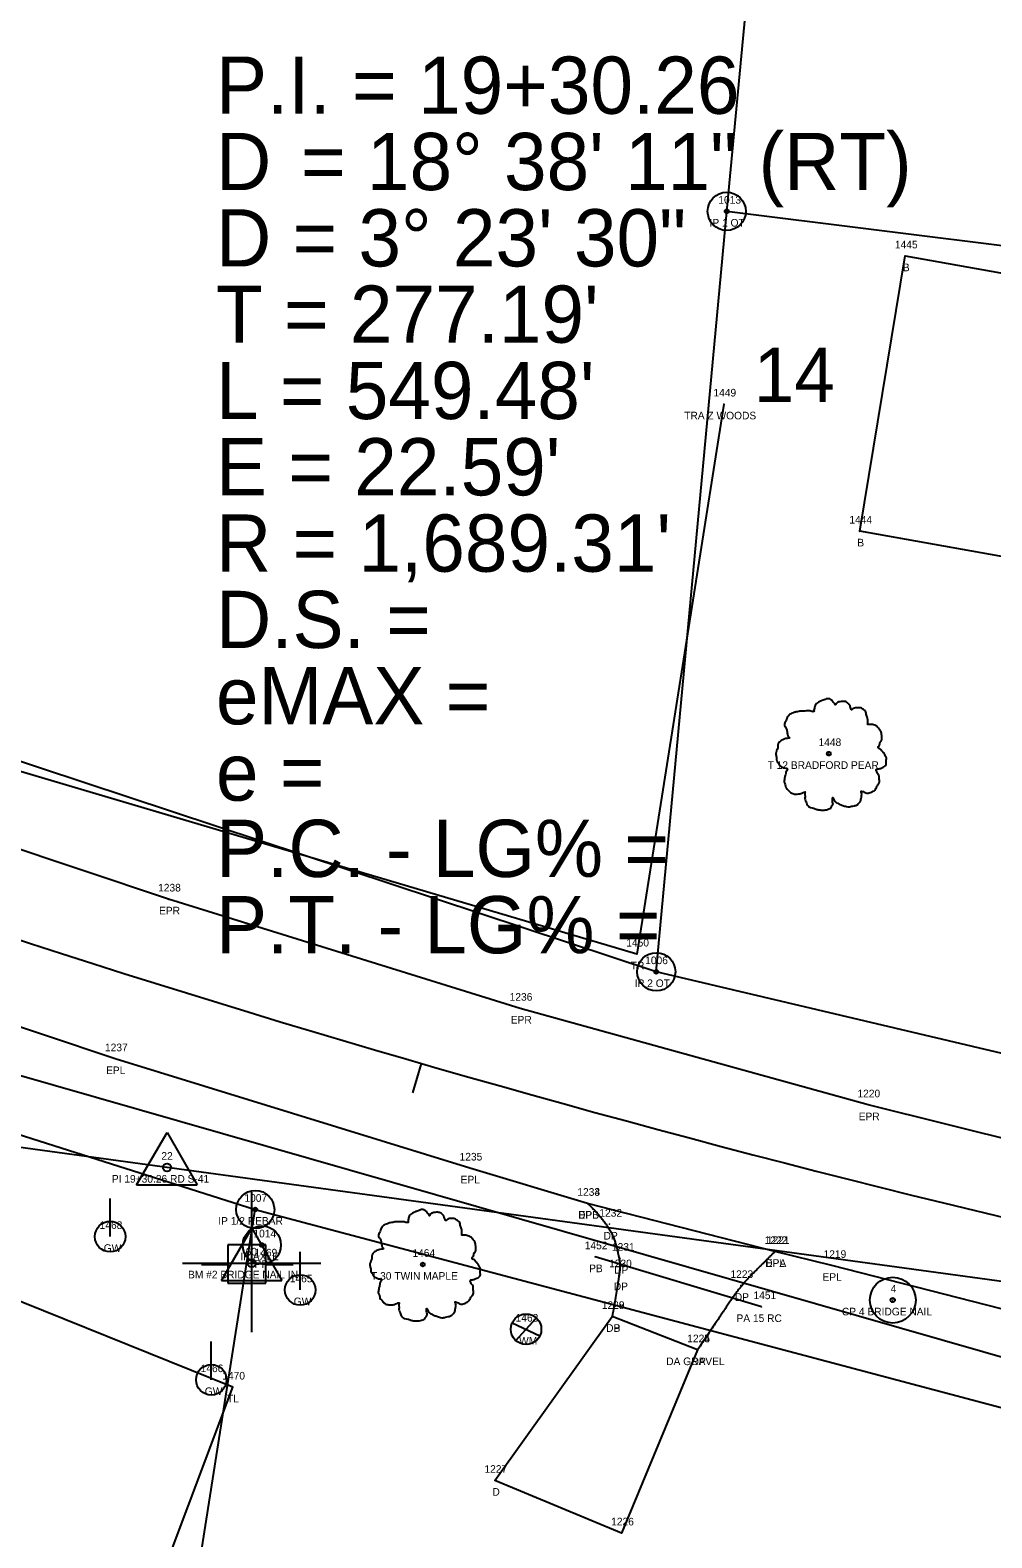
# Model space of a CAD drawing. Extents: x 1812113 to 1819860, y 1177395 to 1181185.
# Drawn here: x 1813245.7 to 1813371.7, y 1178760.4 to 1178958 of the extents above; entities that cross this region are included whole.
import ezdxf

# ---------------------------------------------------------------- set-up
doc = ezdxf.new("R2010")
doc.units = 0
for name, color, linetype in [('RD_EX_Bldg', 7, 'Continuous'), ('RD_EX_Bldg_txCode', 7, 'Continuous'), ('RD_EX_DR_Pipe', 7, 'Continuous'), ('RD_EX_DR_Pipe_txCode', 7, 'Continuous'), ('RD_EX_Driveway', 7, 'Continuous'), ('RD_EX_Driveway_txCode', 7, 'Continuous'), ('RD_EX_DV_Prop', 7, 'Continuous'), ('RD_EX_DV_Prop_txCode', 7, 'Continuous'), ('RD_EX_DV_PropPin', 7, 'Continuous'), ('RD_EX_DV_TX_Prop', 7, 'Continuous'), ('RD_EX_Road', 7, 'Continuous'), ('RD_EX_Road_txCode', 7, 'Continuous'), ('RD_EX_UT', 7, 'Continuous'), ('RD_EX_UT_txCode', 7, 'Continuous'), ('RD_EX_VEG', 7, 'Continuous'), ('RD_EX_VEG_txCode', 7, 'Continuous'), ('RD_HC_CL', 7, 'Continuous'), ('RD_HC_Data', 7, 'Continuous'), ('RD_HC_Data_Tic', 7, 'Continuous'), ('RD_HC_TX_StaOther', 7, 'Continuous'), ('RD_HC_txCode', 7, 'Continuous'), ('RD_PD_PatLn1', 7, 'Continuous'), ('RD_SMD_Locator', 7, 'Continuous')]:
    doc.layers.add(name, color=color, linetype=linetype)

msp = doc.modelspace()

# ---------------------------------------------------------------- linework, layer by layer
at = {"layer": 'RD_EX_Bldg'}
msp.add_lwpolyline([(1813386.16, 1178886.63), (1813354.34, 1178892.31), (1813360.31, 1178928.37), (1813392.12, 1178922.69), (1813386.16, 1178886.63)], dxfattribs=at)
at = {"layer": 'RD_EX_DR_Pipe'}
msp.add_line((1813341.49, 1178790.69), (1813319.67, 1178797.22), dxfattribs=at)
at = {"layer": 'RD_EX_Driveway'}
msp.add_line((1813333.1, 1178785.04), (1813321.9, 1178789.4), dxfattribs=at)
msp.add_lwpolyline([(1813333.1, 1178785.04), (1813323.15, 1178761.04), (1813306.52, 1178767.93), (1813321.9, 1178789.4)], dxfattribs=at)
for points in [[(1813318.7, 1178804.23), (1813321.57, 1178801.49), (1813322.95, 1178797.03), (1813322.9, 1178794.86), (1813321.9, 1178789.4)], [(1813343.23, 1178797.92), (1813341, 1178795.69), (1813338.76, 1178793.46), (1813335.93, 1178789.25), (1813333.1, 1178785.04)]]:
    msp.add_open_spline(points, degree=2, dxfattribs=at)
at = {"layer": 'RD_EX_DV_Prop'}
for p, q in [((1813336.92, 1178934.22), (1813350.46, 1179077.16)), ((1813327.69, 1178834.58), (1813336.92, 1178934.22)), ((1813428.23, 1178922.79), (1813336.92, 1178934.22)), ((1813327.69, 1178834.58), (1813191.92, 1178879.48)), ((1813136.34, 1178847.55), (1813275.15, 1178803.43)), ((1813400.47, 1178817.38), (1813327.69, 1178834.58)), ((1813247.98, 1178630.56), (1813275.15, 1178803.43)), ((1813275.15, 1178803.43), (1813409.98, 1178767.65))]:
    msp.add_line(p, q, dxfattribs=at)
at = {"layer": 'RD_EX_DV_PropPin'}
for centre, radius in [((1813336.92, 1178934.22), 2.5), ((1813336.92, 1178934.22), 0.25), ((1813327.69, 1178834.58), 2.5), ((1813327.69, 1178834.58), 0.25), ((1813275.15, 1178803.43), 2.5), ((1813275.15, 1178803.43), 0.25), ((1813276.02, 1178798.78), 2.5), ((1813276.02, 1178798.78), 0.25)]:
    msp.add_circle(centre, radius, dxfattribs=at)
at = {"layer": 'RD_EX_Road'}
for p, q in [((1813263.76, 1178844.1), (1813216.84, 1178859.81)), ((1813309.85, 1178829.79), (1813263.76, 1178844.1)), ((1813355.44, 1178817.13), (1813309.85, 1178829.79)), ((1813398.64, 1178806.42), (1813355.44, 1178817.13))]:
    msp.add_line(p, q, dxfattribs=at)
msp.add_lwpolyline([(1813732.94, 1178707.95), (1813689.88, 1178731.75), (1813641.71, 1178744.36), (1813593.37, 1178752.09), (1813544.49, 1178758.77), (1813495.45, 1178766.29), (1813446.8, 1178774.66), (1813426.54, 1178777.95), (1813403.21, 1178782.55), (1813398.65, 1178783.84), (1813350.68, 1178796.09), (1813343.23, 1178797.92), (1813318.7, 1178804.23), (1813303.26, 1178808.85), (1813256.8, 1178823.17), (1813209.81, 1178838.91), (1813163.27, 1178855.57)], dxfattribs=at)
at = {"layer": 'RD_EX_UT'}
for p, q in [((1813256.13, 1178799.88), (1813256.13, 1178804.88)), ((1813276.55, 1178798.79), (1813271.55, 1178798.79)), ((1813271.55, 1178798.79), (1813271.55, 1178793.79)), ((1813276.55, 1178793.79), (1813276.55, 1178798.79)), ((1813281.04, 1178792.89), (1813281.04, 1178797.89)), ((1813268.12, 1178796.23), (1813271.59, 1178796.23)), ((1813276.48, 1178796.23), (1813280.12, 1178796.23)), ((1813271.55, 1178793.79), (1813276.55, 1178793.79)), ((1813309.28, 1178786.28), (1813311.94, 1178789.18)), ((1813308.79, 1178788.58), (1813312.43, 1178786.87)), ((1813269.39, 1178781.12), (1813269.39, 1178786.12))]:
    msp.add_line(p, q, dxfattribs=at)
msp.add_lwpolyline([(1812996.89, 1178919.95), (1813204.49, 1178832.44), (1813481.3, 1178753.03), (1813490.2, 1178706.76)], dxfattribs=at)
for centre in [(1813256.13, 1178799.88), (1813281.04, 1178792.89), (1813310.63, 1178787.74), (1813269.39, 1178781.12)]:
    msp.add_circle(centre, 2, dxfattribs=at)
at = {"layer": 'RD_EX_VEG'}
for points in [[(1813336.53, 1178908.96), (1813325.15, 1178836.89), (1813188.47, 1178877.39), (1813208.68, 1178923.85)], [(1813260.51, 1178748.95), (1813272.22, 1178780.15), (1813153.76, 1178827.9)]]:
    msp.add_lwpolyline(points, dxfattribs=at)
for centre, radius in [((1813350.3, 1178863.16), 0.25), ((1813350.28, 1178863.14), 0.0001), ((1813297.11, 1178796.23), 0.25), ((1813297.1, 1178796.21), 0.0001)]:
    msp.add_circle(centre, radius, dxfattribs=at)
for points in [[(1813350.43, 1178870.33), (1813350.13, 1178870.36), (1813349.8, 1178870.26), (1813349.55, 1178870.16), (1813349.33, 1178870.08), (1813349.1, 1178869.98), (1813348.8, 1178869.81), (1813348.58, 1178869.61), (1813348.45, 1178869.36), (1813348.4, 1178869.13), (1813348.35, 1178868.86), (1813348.35, 1178868.68), (1813348.23, 1178868.66), (1813348.08, 1178868.68), (1813347.83, 1178868.76), (1813347.58, 1178868.76), (1813347.33, 1178868.76), (1813346.98, 1178868.73), (1813346.63, 1178868.73), (1813346.35, 1178868.68), (1813346.03, 1178868.63), (1813345.65, 1178868.51), (1813345.3, 1178868.38), (1813345, 1178868.13), (1813344.75, 1178867.66), (1813344.63, 1178867.31), (1813344.48, 1178867.06), (1813344.63, 1178866.61), (1813344.8, 1178866.26), (1813344.83, 1178866.06), (1813344.9, 1178865.63), (1813345, 1178865.41), (1813345.13, 1178865.21), (1813345.05, 1178865.18), (1813344.68, 1178865.13), (1813344.38, 1178865.03), (1813343.95, 1178864.81), (1813343.73, 1178864.58), (1813343.63, 1178864.26), (1813343.61, 1178863.91), (1813343.51, 1178863.71), (1813343.43, 1178863.43), (1813343.41, 1178863.36), (1813343.36, 1178863.03), (1813343.46, 1178862.58), (1813343.48, 1178862.23), (1813343.61, 1178862.01), (1813343.75, 1178861.83), (1813343.93, 1178861.58), (1813344.33, 1178861.36), (1813344.65, 1178861.26), (1813344.85, 1178861.23), (1813344.68, 1178860.73), (1813344.63, 1178860.38), (1813344.5, 1178859.98), (1813344.5, 1178859.91), (1813344.45, 1178859.43), (1813344.6, 1178859.11), (1813344.68, 1178858.74), (1813344.85, 1178858.51), (1813345.13, 1178858.21), (1813345.45, 1178857.99), (1813345.95, 1178857.86), (1813346.35, 1178857.89), (1813346.93, 1178858.06), (1813347.18, 1178858.14), (1813347.15, 1178857.96), (1813347.18, 1178857.59), (1813347.18, 1178857.16), (1813347.33, 1178856.84), (1813347.43, 1178856.56), (1813347.58, 1178856.31), (1813347.9, 1178856.09), (1813348.3, 1178856.01), (1813348.73, 1178855.86), (1813349.18, 1178855.79), (1813349.68, 1178855.76), (1813350.28, 1178855.91), (1813350.55, 1178856.04), (1813350.65, 1178856.21), (1813350.85, 1178856.59), (1813350.8, 1178856.81), (1813350.83, 1178857.41), (1813350.93, 1178857.24), (1813351.1, 1178856.89), (1813351.6, 1178856.59), (1813352, 1178856.41), (1813352.48, 1178856.26), (1813352.78, 1178856.19), (1813353.25, 1178856.26), (1813353.63, 1178856.34), (1813354, 1178856.46), (1813354.3, 1178856.74), (1813354.48, 1178857.01), (1813354.53, 1178857.29), (1813354.6, 1178857.66), (1813354.65, 1178857.84)], [(1813354.65, 1178857.84), (1813354.58, 1178858.01), (1813354.53, 1178858.26), (1813354.6, 1178858.24), (1813354.78, 1178858.19), (1813355.05, 1178858.06), (1813355.27, 1178857.99), (1813355.6, 1178858.01), (1813355.87, 1178858.11), (1813356.32, 1178858.39), (1813356.6, 1178858.86), (1813356.87, 1178859.26), (1813356.95, 1178859.58), (1813356.9, 1178859.81), (1813356.87, 1178860.31), (1813356.67, 1178860.56), (1813356.62, 1178860.68), (1813356.52, 1178861.08), (1813356.6, 1178861.13), (1813356.87, 1178861.18), (1813357.25, 1178861.31), (1813357.52, 1178861.43), (1813357.75, 1178861.61), (1813357.82, 1178861.83), (1813357.8, 1178862.23), (1813357.85, 1178862.63), (1813357.77, 1178862.78), (1813357.67, 1178862.93), (1813357.6, 1178863.13), (1813357.45, 1178863.28), (1813357.35, 1178863.43), (1813357.25, 1178863.53), (1813357.12, 1178863.68), (1813356.95, 1178863.81), (1813356.8, 1178863.86), (1813356.75, 1178864.01), (1813356.9, 1178864.21), (1813356.95, 1178864.31), (1813356.97, 1178864.53), (1813357.2, 1178864.88), (1813357.25, 1178865.28), (1813357.2, 1178865.71), (1813357.15, 1178865.98), (1813357, 1178866.26), (1813356.8, 1178866.51), (1813356.67, 1178866.68), (1813356.5, 1178866.81), (1813356.17, 1178866.93), (1813355.92, 1178866.98), (1813355.57, 1178866.98), (1813355.37, 1178867.03), (1813355.4, 1178867.08), (1813355.4, 1178867.23), (1813355.4, 1178867.51), (1813355.32, 1178867.96), (1813355.17, 1178868.46), (1813355.17, 1178868.48), (1813355.07, 1178868.73), (1813354.85, 1178868.93), (1813354.68, 1178869.03), (1813354.48, 1178869.16), (1813354.23, 1178869.18), (1813353.93, 1178869.18), (1813353.65, 1178869.13), (1813353.45, 1178869.03), (1813353.28, 1178868.91), (1813353.2, 1178869.06), (1813353.1, 1178869.36), (1813353.05, 1178869.51), (1813352.9, 1178869.68), (1813352.68, 1178869.88), (1813352.23, 1178870.01), (1813351.6, 1178869.93), (1813351.3, 1178869.73), (1813351.15, 1178869.56), (1813351.1, 1178869.68), (1813350.9, 1178869.88), (1813350.8, 1178870.06), (1813350.63, 1178870.18), (1813350.48, 1178870.28), (1813350.38, 1178870.33)], [(1813297.24, 1178803.4), (1813296.94, 1178803.42), (1813296.62, 1178803.32), (1813296.37, 1178803.22), (1813296.14, 1178803.15), (1813295.92, 1178803.05), (1813295.62, 1178802.87), (1813295.39, 1178802.67), (1813295.27, 1178802.42), (1813295.22, 1178802.2), (1813295.17, 1178801.92), (1813295.17, 1178801.75), (1813295.04, 1178801.72), (1813294.89, 1178801.75), (1813294.64, 1178801.82), (1813294.39, 1178801.82), (1813294.14, 1178801.82), (1813293.79, 1178801.8), (1813293.44, 1178801.8), (1813293.17, 1178801.75), (1813292.84, 1178801.7), (1813292.47, 1178801.57), (1813292.12, 1178801.45), (1813291.82, 1178801.2), (1813291.57, 1178800.72), (1813291.44, 1178800.37), (1813291.29, 1178800.12), (1813291.44, 1178799.67), (1813291.62, 1178799.32), (1813291.64, 1178799.12), (1813291.72, 1178798.7), (1813291.82, 1178798.48), (1813291.94, 1178798.28), (1813291.87, 1178798.25), (1813291.49, 1178798.2), (1813291.19, 1178798.1), (1813290.77, 1178797.88), (1813290.54, 1178797.65), (1813290.44, 1178797.33), (1813290.42, 1178796.98), (1813290.32, 1178796.78), (1813290.24, 1178796.5), (1813290.22, 1178796.43), (1813290.17, 1178796.1), (1813290.27, 1178795.65), (1813290.29, 1178795.3), (1813290.42, 1178795.08), (1813290.57, 1178794.9), (1813290.74, 1178794.65), (1813291.14, 1178794.43), (1813291.47, 1178794.33), (1813291.67, 1178794.3), (1813291.49, 1178793.8), (1813291.44, 1178793.45), (1813291.32, 1178793.05), (1813291.32, 1178792.98), (1813291.27, 1178792.5), (1813291.42, 1178792.18), (1813291.49, 1178791.8), (1813291.67, 1178791.58), (1813291.94, 1178791.28), (1813292.27, 1178791.05), (1813292.77, 1178790.93), (1813293.17, 1178790.95), (1813293.74, 1178791.13), (1813293.99, 1178791.2), (1813293.97, 1178791.03), (1813293.99, 1178790.65), (1813293.99, 1178790.23), (1813294.14, 1178789.9), (1813294.24, 1178789.63), (1813294.39, 1178789.38), (1813294.72, 1178789.15), (1813295.12, 1178789.08), (1813295.54, 1178788.93), (1813295.99, 1178788.85), (1813296.49, 1178788.83), (1813297.09, 1178788.98), (1813297.37, 1178789.1), (1813297.47, 1178789.28), (1813297.67, 1178789.65), (1813297.62, 1178789.88), (1813297.64, 1178790.48), (1813297.74, 1178790.3), (1813297.91, 1178789.95), (1813298.41, 1178789.65), (1813298.81, 1178789.48), (1813299.29, 1178789.33), (1813299.59, 1178789.25), (1813300.06, 1178789.33), (1813300.44, 1178789.4), (1813300.81, 1178789.53), (1813301.11, 1178789.8), (1813301.29, 1178790.08), (1813301.34, 1178790.35), (1813301.41, 1178790.73), (1813301.46, 1178790.9)], [(1813301.46, 1178790.9), (1813301.39, 1178791.08), (1813301.34, 1178791.33), (1813301.41, 1178791.3), (1813301.59, 1178791.25), (1813301.86, 1178791.13), (1813302.09, 1178791.05), (1813302.41, 1178791.08), (1813302.69, 1178791.18), (1813303.14, 1178791.45), (1813303.41, 1178791.93), (1813303.69, 1178792.33), (1813303.76, 1178792.65), (1813303.71, 1178792.88), (1813303.69, 1178793.38), (1813303.49, 1178793.63), (1813303.44, 1178793.75), (1813303.34, 1178794.15), (1813303.41, 1178794.2), (1813303.69, 1178794.25), (1813304.06, 1178794.38), (1813304.34, 1178794.5), (1813304.56, 1178794.68), (1813304.64, 1178794.9), (1813304.61, 1178795.3), (1813304.66, 1178795.7), (1813304.59, 1178795.85), (1813304.49, 1178796), (1813304.41, 1178796.2), (1813304.26, 1178796.35), (1813304.16, 1178796.5), (1813304.06, 1178796.6), (1813303.94, 1178796.75), (1813303.76, 1178796.88), (1813303.61, 1178796.93), (1813303.56, 1178797.08), (1813303.71, 1178797.28), (1813303.76, 1178797.38), (1813303.79, 1178797.6), (1813304.01, 1178797.95), (1813304.06, 1178798.35), (1813304.01, 1178798.78), (1813303.96, 1178799.05), (1813303.81, 1178799.32), (1813303.61, 1178799.57), (1813303.49, 1178799.75), (1813303.31, 1178799.87), (1813302.99, 1178800), (1813302.74, 1178800.05), (1813302.39, 1178800.05), (1813302.19, 1178800.1), (1813302.21, 1178800.15), (1813302.21, 1178800.3), (1813302.21, 1178800.57), (1813302.14, 1178801.02), (1813301.99, 1178801.52), (1813301.99, 1178801.55), (1813301.89, 1178801.8), (1813301.66, 1178802), (1813301.49, 1178802.1), (1813301.29, 1178802.22), (1813301.04, 1178802.25), (1813300.74, 1178802.25), (1813300.46, 1178802.2), (1813300.26, 1178802.1), (1813300.09, 1178801.97), (1813300.01, 1178802.12), (1813299.91, 1178802.42), (1813299.86, 1178802.57), (1813299.71, 1178802.75), (1813299.49, 1178802.95), (1813299.04, 1178803.07), (1813298.41, 1178803), (1813298.11, 1178802.8), (1813297.96, 1178802.62), (1813297.91, 1178802.75), (1813297.71, 1178802.95), (1813297.62, 1178803.12), (1813297.44, 1178803.25), (1813297.29, 1178803.35), (1813297.19, 1178803.4)]]:
    msp.add_spline(points, degree=3, dxfattribs=at)
at = {"layer": 'RD_HC_CL'}
msp.add_arc((1813766.93, 1180445.18), 1689.31, 243.58271, 262.2191, dxfattribs=at)
at = {"layer": 'RD_HC_Data'}
for p, q in [((1813259.61, 1178806.65), (1813263.59, 1178813.53)), ((1813263.59, 1178813.53), (1813267.55, 1178806.65)), ((1813259.61, 1178806.65), (1813267.55, 1178806.65)), ((1813274.68, 1178787.37), (1813274.68, 1178805.7)), ((1813270.71, 1178794.12), (1813274.68, 1178801)), ((1813274.68, 1178801), (1813278.65, 1178794.12)), ((1813265.63, 1178796.41), (1813283.72, 1178796.41)), ((1813270.71, 1178794.12), (1813278.65, 1178794.12))]:
    msp.add_line(p, q, dxfattribs=at)
for centre, radius in [((1813263.59, 1178808.95), 0.529), ((1813274.68, 1178796.41), 0.529), ((1813358.68, 1178791.56), 3), ((1813358.68, 1178791.56), 0.282)]:
    msp.add_circle(centre, radius, dxfattribs=at)
at = {"layer": 'RD_HC_Data_Tic'}
msp.add_line((1813296.88, 1178822.58), (1813295.76, 1178818.74), dxfattribs=at)
at = {"layer": 'RD_PD_PatLn1'}
msp.add_line((1813616.11, 1178760.78), (1813027.99, 1178841.14), dxfattribs=at)
at = {"layer": 'RD_SMD_Locator'}
for centre in [(1813360.31, 1178928.37), (1813336.53, 1178908.96), (1813354.34, 1178892.31), (1813263.76, 1178844.1), (1813325.15, 1178836.89), (1813309.85, 1178829.79), (1813256.8, 1178823.17), (1813355.44, 1178817.13), (1813263.59, 1178808.95), (1813303.26, 1178808.85), (1813318.7, 1178804.23), (1813318.7, 1178804.23), (1813321.57, 1178801.49), (1813319.67, 1178797.22), (1813322.95, 1178797.03), (1813343.23, 1178797.92), (1813343.23, 1178797.92), (1813274.68, 1178796.41), (1813322.9, 1178794.86), (1813350.68, 1178796.09), (1813338.76, 1178793.46), (1813358.68, 1178791.56), (1813321.9, 1178789.4), (1813321.9, 1178789.4), (1813341.49, 1178790.69), (1813333.1, 1178785.04), (1813333.1, 1178785.04), (1813272.22, 1178780.15), (1813306.52, 1178767.93), (1813323.15, 1178761.04)]:
    msp.add_circle(centre, 0.001, dxfattribs=at)

# ---------------------------------------------------------------- texts
at = {"layer": 'RD_EX_Bldg_txCode'}
for s, p in [('1445', (1813358.96, 1178929.37)), ('B', (1813360, 1178926.37)), ('1444', (1813352.99, 1178893.31)), ('B', (1813354.03, 1178890.31))]:
    msp.add_text(s, height=1, dxfattribs=at).set_placement(p)
at = {"layer": 'RD_EX_DR_Pipe_txCode'}
for s, p in [('1452', (1813318.32, 1178798.22)), ('PB', (1813318.89, 1178795.22)), ('1451', (1813340.43, 1178791.69)), ('PA 15 RC', (1813338.2, 1178788.69))]:
    msp.add_text(s, height=1, dxfattribs=at).set_placement(p)
at = {"layer": 'RD_EX_Driveway_txCode'}
for s, p in [('1233', (1813317.35, 1178805.23)), ('DPB', (1813317.44, 1178802.23)), ('1232', (1813320.23, 1178802.49)), ('DP', (1813320.79, 1178799.49)), ('1231', (1813321.88, 1178798.03)), ('1222', (1813341.89, 1178798.92)), ('1230', (1813321.51, 1178795.86)), ('DPA', (1813341.97, 1178795.92)), ('DP', (1813322.17, 1178795.03)), ('1223', (1813337.41, 1178794.46)), ('DP', (1813322.12, 1178792.86)), ('1228', (1813320.55, 1178790.4)), ('1229', (1813320.55, 1178790.4)), ('DP', (1813337.98, 1178791.46)), ('DB', (1813321.12, 1178787.4)), ('DP', (1813321.12, 1178787.4)), ('1224', (1813331.75, 1178786.04)), ('1225', (1813331.75, 1178786.04)), ('DA GRAVEL', (1813328.99, 1178783.04)), ('DP', (1813332.32, 1178783.04)), ('1227', (1813305.18, 1178768.93)), ('D', (1813306.22, 1178765.93)), ('1226', (1813321.78, 1178762.04))]:
    msp.add_text(s, height=1, dxfattribs=at).set_placement(p)
at = {"layer": 'RD_EX_DV_Prop_txCode'}
for s, p in [('1013', (1813335.82, 1178935.22)), ('IP 1 OT', (1813334.67, 1178932.22)), ('1006', (1813326.24, 1178835.58)), ('IP 2 OT', (1813324.87, 1178832.58)), ('1007', (1813273.73, 1178804.44)), ('IP 1/2 REBAR', (1813270.3, 1178801.44)), ('1014', (1813274.91, 1178799.78)), ('IP AXLE', (1813273.19, 1178796.78))]:
    msp.add_text(s, height=1, dxfattribs=at).set_placement(p)
at = {"layer": 'RD_EX_DV_TX_Prop'}
msp.add_text('14', height=7.14, dxfattribs=at).set_placement((1813340.47, 1178909.22))
at = {"layer": 'RD_EX_Road_txCode'}
for s, p in [('1238', (1813262.42, 1178845.1)), ('EPR', (1813262.54, 1178842.1)), ('1236', (1813308.48, 1178830.79)), ('EPR', (1813308.62, 1178827.79)), ('1237', (1813255.46, 1178824.17)), ('EPL', (1813255.6, 1178821.17)), ('1220', (1813354.05, 1178818.13)), ('EPR', (1813354.21, 1178815.13)), ('1235', (1813301.92, 1178809.85)), ('EPL', (1813302.06, 1178806.85)), ('1234', (1813317.35, 1178805.23)), ('EPL', (1813317.49, 1178802.23)), ('1221', (1813342.17, 1178798.92)), ('EPL', (1813342.03, 1178795.92)), ('1219', (1813349.61, 1178797.09)), ('EPL', (1813349.47, 1178794.09))]:
    msp.add_text(s, height=1, dxfattribs=at).set_placement(p)
at = {"layer": 'RD_EX_UT_txCode'}
for s, p in [('1468', (1813254.76, 1178800.88)), ('GW', (1813255.29, 1178797.88)), ('1469', (1813275.06, 1178797.28)), ('PP', (1813275.06, 1178795.78)), ('1465', (1813279.67, 1178793.89)), ('GW', (1813280.19, 1178790.89)), ('1463', (1813309.26, 1178788.74)), ('WM', (1813309.72, 1178785.74)), ('1466', (1813267.99, 1178782.12)), ('GW', (1813268.54, 1178779.12))]:
    msp.add_text(s, height=1, dxfattribs=at).set_placement(p)
at = {"layer": 'RD_EX_VEG_txCode'}
for s, p in [('1449', (1813335.18, 1178909.96)), ('TRA Z WOODS', (1813331.35, 1178906.96)), ('1448', (1813348.95, 1178864.16)), ('T 12 BRADFORD PEAR', (1813342.28, 1178861.16)), ('1450', (1813323.76, 1178837.89)), ('TR', (1813324.35, 1178834.89)), ('1464', (1813295.74, 1178797.23)), ('T 30 TWIN MAPLE', (1813290.32, 1178794.23)), ('1470', (1813270.83, 1178781.15)), ('TL', (1813271.44, 1178778.15))]:
    msp.add_text(s, height=1, dxfattribs=at).set_placement(p)
at = {"layer": 'RD_HC_TX_StaOther'}
for s, p in [('P.I. = 19+30.26', (1813270, 1178947)), ('    = 18%%d 38\' 11" (RT)', (1813270, 1178937)), ('D', (1813270, 1178937)), ('D = 3%%d 23\' 30"', (1813270, 1178927)), ("T = 277.19'", (1813270, 1178917)), ("L = 549.48'", (1813270, 1178907)), ("E = 22.59'", (1813270, 1178897)), ("R = 1,689.31'", (1813270, 1178887)), ('D.S. = ', (1813270, 1178877)), ('eMAX = ', (1813270, 1178867)), ('e = ', (1813270, 1178857)), ('P.C. - LG% = ', (1813270, 1178847)), ('P.T. - LG% = ', (1813270, 1178837))]:
    msp.add_text(s, height=7.5, dxfattribs=at).set_placement(p)
at = {"layer": 'RD_HC_txCode'}
for s, p in [('22', (1813262.85, 1178809.95)), ('PI 19+30.26 RD S-41', (1813256.36, 1178806.95)), ('60', (1813273.88, 1178797.41)), ('BM #2 BRIDGE NAIL IN', (1813266.34, 1178794.41)), ('4', (1813358.4, 1178792.56)), ('CP 4 BRIDGE NAIL', (1813352.01, 1178789.56))]:
    msp.add_text(s, height=1, dxfattribs=at).set_placement(p)

doc.saveas('drawing.dxf')
